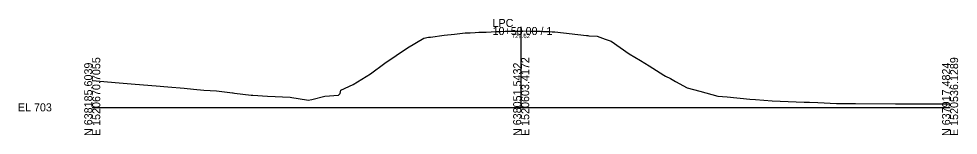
# Model space of a CAD drawing. Extents: x -26 to 303, y -10 to 4521.
# Drawn here: x -25.7 to 302.8, y 490.3 to 530.9 of the extents above; entities that cross this region are included whole.
import ezdxf

# ---------------------------------------------------------------- set-up
doc = ezdxf.new("R2010")
doc.units = 0
for name, color, linetype in [('Default', 7, 'Continuous'), ('Exist Cross Section Cell', 7, 'Continuous'), ('Exist XS Center Line Elevation Label', 7, 'Continuous'), ('Exist XS Ground Line', 7, 'Continuous')]:
    doc.layers.add(name, color=color, linetype=linetype)

msp = doc.modelspace()

# ---------------------------------------------------------------- linework, layer by layer
at = {"layer": 'Exist Cross Section Cell'}
for p, q in [((150, 500), (150, 528.02)), ((0, 500), (150, 500)), ((150, 500), (300, 500))]:
    msp.add_line(p, q, dxfattribs=at)
at = {"layer": 'Exist XS Ground Line'}
msp.add_lwpolyline([(0, 509.34), (9.38, 508.55), (15, 508.1), (22.35, 507.46), (26.43, 507.17), (32.13, 506.66), (35.37, 506.39), (39.04, 506.04), (43.45, 505.73), (49.02, 505.08), (49.31, 505.05), (49.73, 504.98), (55.59, 504.28), (56.13, 504.24), (61.28, 503.85), (69.18, 503.51), (69.77, 503.49), (74.89, 502.58), (75.56, 502.49), (76.8, 502.7), (81.35, 503.92), (86.08, 504.28), (86.73, 504.85), (86.98, 506.05), (91.19, 508), (97.27, 511.74), (102.28, 515.44), (110.26, 520.73), (115.95, 524.12), (117.62, 524.46), (118.32, 524.52), (123.08, 525.13), (126.67, 525.55), (130.4, 526.01), (131.2, 526.01), (131.33, 526.01), (132.21, 526.04), (133.88, 526.11), (135.17, 526.16), (136.67, 526.22), (137.03, 526.24), (137.76, 526.27), (139.47, 526.34), (141.19, 526.42), (142.26, 526.47), (142.87, 526.5), (144.63, 526.6), (144.7, 526.59), (145.03, 526.6), (147.82, 526.62), (148.18, 526.62), (148.9, 526.62), (150.62, 526.62), (151.9, 526.63), (153.42, 526.6), (153.77, 526.59), (154.47, 526.57), (155.64, 526.54), (156.22, 526.52), (156.78, 526.51), (157.53, 526.49), (157.75, 526.48), (159.03, 526.44), (159.88, 526.42), (160.89, 526.39), (161.11, 526.39), (161.19, 526.38), (161.75, 526.35), (172.87, 525.05), (173.31, 525), (173.61, 524.96), (173.7, 524.96), (173.81, 524.95), (176.52, 524.81), (179.33, 523.78), (181.46, 523.04), (184.62, 520.84), (187.76, 518.71), (191.71, 516.35), (194.75, 514.49), (199.85, 511.27), (200.42, 510.91), (202.17, 510.1), (203.96, 509.05), (208.02, 506.76), (212.47, 505.61), (218.83, 503.9), (222.07, 503.66), (229.98, 502.85), (231.9, 502.73), (237.81, 502.27), (248.99, 501.85), (250.87, 501.79), (253.7, 501.69), (260.25, 501.39), (260.82, 501.37), (266.88, 501.3), (280.89, 501.22), (284.85, 501.21), (285.55, 501.2), (287.59, 501.21), (299.12, 501.18), (300, 501.17)], dxfattribs=at)

# ---------------------------------------------------------------- texts
at = {"layer": 'Default'}
msp.add_text('-', height=0.0001, dxfattribs=at).set_placement((0, 500))
at = {"layer": 'Exist Cross Section Cell'}
for s, p in [('LPC', (140, 528.02)), ('10+50.00 / 1', (140, 525.22)), ('EL 703', (-26, 498.6))]:
    msp.add_text(s, height=2.8, dxfattribs=at).set_placement(p)
for s, p in [('E 1520670.7055', (2.8, 490)), ('E 1520603.4172', (152.8, 490)), ('E 1520536.1289', (302.8, 490)), ('N 638185.6039', (0, 490)), ('N 638051.5432', (150, 490)), ('N 637917.4824', (300, 490))]:
    msp.add_text(s, height=2.8, rotation=90, dxfattribs=at).set_placement(p)
at = {"layer": 'Exist XS Center Line Elevation Label'}
msp.add_text('729.62', height=1.5, dxfattribs=at).set_placement((146.74, 524.14))

doc.saveas('drawing.dxf')
